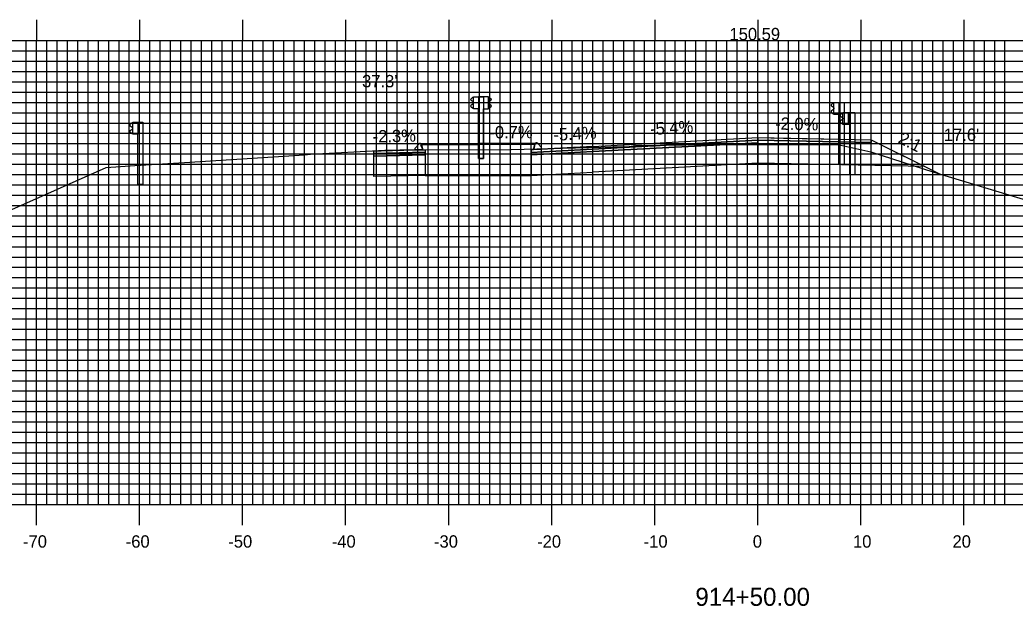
# Model space of a CAD drawing. Extents: x 860652 to 860995, y 364765 to 364985.
# Drawn here: x 860745.8 to 860842.4, y 364833.4 to 364890.3 of the extents above; entities that cross this region are included whole.
import ezdxf

# ---------------------------------------------------------------- set-up
doc = ezdxf.new("R2010")
doc.units = 0
for name, color, linetype in [('ANNOTATION', 7, 'Continuous'), ('D_Curb_Type_3M2_Lt', 7, 'Continuous'), ('D_Curb_Type_3M2_Rt', 7, 'Continuous'), ('D_Guardrail_Beam_Rt', 7, 'Continuous'), ('D_Roadway_Centerline', 7, 'Continuous'), ('D_Roadway_Centerline_Text', 7, 'Continuous'), ('D_Roadway_Edge_Shoulder', 7, 'Continuous'), ('D_Roadway_Edge_TW', 7, 'Continuous'), ('D_Roadway_FinishedGrade', 7, 'Continuous'), ('D_Roadway_Pavement', 7, 'Continuous'), ('D_Roadway_SlopeLines', 7, 'Continuous'), ('D_Roadway_SubGrade', 7, 'Continuous'), ('D_Text_Standard', 7, 'Continuous'), ('H_V ANNOTATION', 7, 'Continuous'), ('M_Guardrail', 7, 'Continuous'), ('M_Roadway_Centerline', 7, 'Continuous'), ('MAJOR', 7, 'Continuous'), ('MINOR', 7, 'Continuous'), ('S_Roadway_Centerline', 7, 'Continuous')]:
    doc.layers.add(name, color=color, linetype=linetype)

msp = doc.modelspace()

# ---------------------------------------------------------------- linework, layer by layer
at = {"layer": 'D_Curb_Type_3M2_Lt'}
for p, q in [((860795.77, 364878.255), (860795.662, 364877.761)), ((860795.662, 364877.761), (860796.412, 364877.761)), ((860795.906, 364878.384), (860795.911, 364878.384)), ((860796.412, 364877.928), (860796.058, 364878.33)), ((860796.412, 364877.761), (860796.412, 364877.928))]:
    msp.add_line(p, q, dxfattribs=at)
msp.add_arc((860795.933, 364878.22), 0.167, 41.38705, 167.66476, dxfattribs=at)
at = {"layer": 'D_Curb_Type_3M2_Rt'}
for p, q in [((860784.145, 364877.859), (860784.499, 364878.261)), ((860784.145, 364877.692), (860784.145, 364877.859)), ((860784.895, 364877.692), (860784.145, 364877.692)), ((860784.787, 364878.186), (860784.895, 364877.692))]:
    msp.add_line(p, q, dxfattribs=at)
msp.add_arc((860784.624, 364878.151), 0.167, 12.33524, 138.61295, dxfattribs=at)
at = {"layer": 'D_Guardrail_Beam_Rt'}
for p, q in [((860825.594, 364881.214), (860825.45, 364881.114)), ((860825.45, 364880.971), (860825.646, 364880.835)), ((860825.646, 364880.636), (860825.45, 364880.5)), ((860825.684, 364881.235), (860825.609, 364881.221)), ((860825.679, 364880.77), (860825.679, 364880.7)), ((860825.684, 364881.319), (860826.371, 364881.319)), ((860825.684, 364880.152), (860825.684, 364881.319)), ((860826.204, 364881.319), (860826.204, 364880.152)), ((860826.309, 364881.319), (860826.309, 364880.152)), ((860826.371, 364881.319), (860826.842, 364881.319)), ((860826.371, 364881.319), (860826.371, 364880.152)), ((860826.842, 364881.319), (860826.842, 364875.319)), ((860825.45, 364880.356), (860825.594, 364880.257)), ((860825.609, 364880.25), (860825.684, 364880.235)), ((860826.371, 364880.152), (860825.684, 364880.152)), ((860826.35, 364875.319), (860826.35, 364880.152)), ((860826.35, 364875.319), (860826.842, 364875.319))]:
    msp.add_line(p, q, dxfattribs=at)
for centre, major_axis, start_param, end_param in [((860825.5, 364881.042), (-0.0877, 0), 5.323254, 7.243116), ((860825.5, 364880.428), (-0.0877, 0), 5.323254, 7.243116), ((860825.618, 364881.18), (-0.0417, 0), 4.907132, 5.323254), ((860825.6, 364880.77), (0.0789, 0), 0, 0.959931), ((860825.6, 364880.7), (0.0789, 0), 5.323254, 6.283185), ((860825.618, 364880.29), (-0.0417, 0), 0.959931, 1.376053)]:
    msp.add_ellipse(centre, major_axis=major_axis, ratio=0.995501, start_param=start_param, end_param=end_param, dxfattribs=at)
at = {"layer": 'D_Roadway_Centerline'}
for points in [[(860796.412, 364877.761), (860796.423, 364877.762), (860799.387, 364877.922), (860801.412, 364878.031), (860801.413, 364878.031), (860817.41, 364878.895), (860817.413, 364878.895), (860819.903, 364878.845), (860825.396, 364878.736), (860825.413, 364878.735), (860828.404, 364878.675), (860828.412, 364878.675), (860828.425, 364878.669), (860833.621, 364876.071), (860833.627, 364876.068), (860834.976, 364875.393)], [(860780.145, 364877.601), (860780.858, 364877.618), (860784.145, 364877.692)]]:
    msp.add_lwpolyline(points, dxfattribs=at)
at = {"layer": 'D_Roadway_Edge_Shoulder'}
for points in [[(860817.413, 364878.895), (860825.413, 364878.735), (860825.413, 364878.735), (860828.412, 364878.675), (860828.412, 364878.425), (860817.413, 364878.645)], [(860780.145, 364877.601), (860784.145, 364877.692), (860785.145, 364877.715), (860785.145, 364877.465), (860780.145, 364877.351)], [(860801.413, 364878.031), (860796.412, 364877.761), (860795.413, 364877.707), (860795.413, 364877.457), (860801.413, 364877.781)]]:
    msp.add_lwpolyline(points, close=True, dxfattribs=at)
at = {"layer": 'D_Roadway_Edge_TW'}
msp.add_lwpolyline([(860801.413, 364878.031), (860817.413, 364878.895), (860817.413, 364878.645), (860801.413, 364877.781)], close=True, dxfattribs=at)
at = {"layer": 'D_Roadway_FinishedGrade'}
msp.add_lwpolyline([(860784.666, 364878.312), (860795.891, 364878.381)], dxfattribs=at)
at = {"layer": 'D_Roadway_Pavement'}
for points in [[(860801.413, 364877.781), (860817.413, 364878.645), (860817.413, 364878.395), (860801.413, 364877.531)], [(860801.413, 364877.781), (860795.413, 364877.457), (860795.413, 364877.207), (860801.413, 364877.531)], [(860780.145, 364877.351), (860785.145, 364877.465), (860785.145, 364877.215), (860780.145, 364877.101)]]:
    msp.add_lwpolyline(points, close=True, dxfattribs=at)
msp.add_lwpolyline([(860817.413, 364878.645), (860817.413, 364878.395)], dxfattribs=at)
msp.add_lwpolyline([(860817.413, 364878.645), (860817.413, 364878.395)], dxfattribs=at)
at = {"layer": 'D_Roadway_SlopeLines'}
msp.add_lwpolyline([(860828.412, 364878.675), (860834.976, 364875.393)], dxfattribs=at)
at = {"layer": 'D_Roadway_SubGrade'}
for points in [[(860817.413, 364878.395), (860817.413, 364878.645), (860828.412, 364878.425), (860828.412, 364878.675), (860833.621, 364876.071), (860817.413, 364876.395)], [(860785.145, 364877.715), (860785.145, 364875.215), (860795.413, 364875.207), (860795.413, 364877.207), (860795.413, 364877.457), (860795.413, 364877.707), (860795.653, 364877.72), (860795.761, 364878.213), (860784.667, 364878.145), (860784.891, 364877.709)], [(860801.413, 364877.531), (860817.413, 364878.395), (860817.413, 364876.395), (860801.413, 364875.531)], [(860780.145, 364877.101), (860785.145, 364877.215), (860785.145, 364877.465), (860785.145, 364875.215), (860780.145, 364875.101)], [(860801.413, 364877.531), (860795.413, 364877.207), (860795.413, 364877.457), (860795.413, 364875.207), (860801.413, 364875.531)]]:
    msp.add_lwpolyline(points, close=True, dxfattribs=at)
at = {"layer": 'M_Guardrail'}
for p, q in [((860789.725, 364882.763), (860789.582, 364882.663)), ((860789.582, 364882.52), (860789.777, 364882.384)), ((860789.824, 364882.785), (860789.742, 364882.77)), ((860789.824, 364882.857), (860790.314, 364882.857)), ((860789.824, 364881.691), (860789.824, 364882.857)), ((860790.301, 364882.859), (860790.301, 364876.859)), ((860790.793, 364882.859), (860790.301, 364882.859)), ((860790.314, 364882.857), (860790.805, 364882.857)), ((860790.314, 364882.857), (860790.314, 364881.691)), ((860791.282, 364882.859), (860790.793, 364882.859)), ((860790.793, 364882.859), (860790.793, 364881.692)), ((860790.805, 364882.857), (860790.805, 364876.857)), ((860791.282, 364881.692), (860791.282, 364882.859)), ((860791.282, 364882.786), (860791.364, 364882.771)), ((860791.525, 364882.521), (860791.329, 364882.385)), ((860791.381, 364882.765), (860791.525, 364882.665)), ((860789.777, 364882.164), (860789.582, 364882.028)), ((860789.582, 364881.885), (860789.725, 364881.785)), ((860789.742, 364881.778), (860789.824, 364881.764)), ((860789.811, 364882.32), (860789.811, 364882.229)), ((860790.314, 364881.691), (860789.824, 364881.691)), ((860790.314, 364876.857), (860790.314, 364881.691)), ((860790.793, 364876.859), (860790.793, 364881.692)), ((860790.793, 364881.692), (860791.282, 364881.692)), ((860791.364, 364881.779), (860791.282, 364881.765)), ((860791.296, 364882.321), (860791.296, 364882.23)), ((860791.329, 364882.165), (860791.525, 364882.029)), ((860791.525, 364881.886), (860791.381, 364881.786)), ((860824.708, 364882.213), (860824.565, 364882.113)), ((860824.565, 364881.97), (860824.76, 364881.834)), ((860824.76, 364881.614), (860824.565, 364881.478)), ((860824.807, 364882.234), (860824.725, 364882.22)), ((860824.794, 364881.77), (860824.794, 364881.678)), ((860824.807, 364882.307), (860825.297, 364882.307)), ((860824.807, 364881.141), (860824.807, 364882.307)), ((860825.297, 364882.307), (860825.788, 364882.307)), ((860825.297, 364882.307), (860825.297, 364881.141)), ((860825.788, 364882.307), (860825.788, 364876.307)), ((860824.565, 364881.335), (860824.708, 364881.235)), ((860824.725, 364881.228), (860824.807, 364881.214)), ((860825.297, 364881.141), (860824.807, 364881.141)), ((860825.297, 364876.307), (860825.297, 364881.141)), ((860756.645, 364880.285), (860756.502, 364880.185)), ((860756.502, 364880.042), (860756.697, 364879.906)), ((860756.697, 364879.686), (860756.502, 364879.55)), ((860756.744, 364880.306), (860756.662, 364880.292)), ((860756.731, 364879.841), (860756.731, 364879.75)), ((860756.744, 364880.379), (860757.234, 364880.379)), ((860756.744, 364879.213), (860756.744, 364880.379)), ((860757.234, 364880.379), (860757.725, 364880.379)), ((860757.234, 364880.379), (860757.234, 364879.213)), ((860757.725, 364880.379), (860757.725, 364874.379)), ((860756.502, 364879.407), (860756.645, 364879.307)), ((860756.662, 364879.3), (860756.744, 364879.285)), ((860757.234, 364879.213), (860756.744, 364879.213)), ((860757.234, 364874.379), (860757.234, 364879.213)), ((860790.793, 364876.859), (860790.301, 364876.859)), ((860790.314, 364876.857), (860790.805, 364876.857)), ((860825.297, 364876.307), (860825.788, 364876.307)), ((860757.234, 364874.379), (860757.725, 364874.379))]:
    msp.add_line(p, q, dxfattribs=at)
for centre, major_axis, start_param, end_param in [((860789.632, 364882.592), (-0.0877, 0), 5.323254, 7.243116), ((860789.749, 364882.729), (-0.0417, 0), 4.886922, 5.323254), ((860791.357, 364882.731), (0.0417, 0), 0.959931, 1.396263), ((860791.474, 364882.593), (0.0877, 0), 5.323254, 7.243116), ((860789.632, 364881.957), (-0.0877, 0), 5.323254, 7.243116), ((860789.749, 364881.819), (-0.0417, 0), 0.959931, 1.396263), ((860789.732, 364882.32), (0.0789, 0), 0, 0.959931), ((860789.732, 364882.229), (0.0789, 0), 5.323254, 6.283185), ((860791.374, 364882.321), (-0.0789, 0), 5.323254, 6.283185), ((860791.374, 364882.23), (-0.0789, 0), 6.283185, 7.243116), ((860791.357, 364881.82), (0.0417, 0), 4.886922, 5.323254), ((860791.474, 364881.958), (0.0877, 0), 5.323254, 7.243116), ((860824.615, 364882.042), (-0.0877, 0), 5.323254, 7.243116), ((860824.615, 364881.406), (-0.0877, 0), 5.323254, 7.243116), ((860824.732, 364882.179), (-0.0417, 0), 4.886922, 5.323254), ((860824.715, 364881.77), (0.0789, 0), 0, 0.959931), ((860824.715, 364881.678), (0.0789, 0), 5.323254, 6.283185), ((860824.732, 364881.269), (-0.0417, 0), 0.959931, 1.396263), ((860756.552, 364880.113), (-0.0877, 0), 5.323254, 7.243116), ((860756.552, 364879.478), (-0.0877, 0), 5.323254, 7.243116), ((860756.669, 364880.251), (-0.0417, 0), 4.886922, 5.323254), ((860756.652, 364879.841), (0.0789, 0), 0, 0.959931), ((860756.652, 364879.75), (0.0789, 0), 5.323254, 6.283185), ((860756.669, 364879.341), (-0.0417, 0), 0.959931, 1.396263)]:
    msp.add_ellipse(centre, major_axis=major_axis, ratio=0.995501, start_param=start_param, end_param=end_param, dxfattribs=at)
at = {"layer": 'MAJOR'}
for p, q in [((860747.412, 364890.306), (860747.412, 364888.302)), ((860757.412, 364890.306), (860757.412, 364888.302)), ((860767.412, 364890.306), (860767.412, 364888.302)), ((860777.412, 364890.306), (860777.412, 364888.302)), ((860787.412, 364890.306), (860787.412, 364888.302)), ((860797.412, 364890.306), (860797.412, 364888.302)), ((860807.412, 364890.306), (860807.412, 364888.302)), ((860817.412, 364890.306), (860817.412, 364888.302)), ((860827.412, 364890.306), (860827.412, 364888.302)), ((860837.412, 364890.306), (860837.412, 364888.302)), ((860677.412, 364888.302), (860957.412, 364888.302)), ((860677.412, 364888.302), (860957.412, 364888.302)), ((860747.412, 364843.302), (860747.412, 364888.302)), ((860757.412, 364843.302), (860757.412, 364888.302)), ((860767.412, 364843.302), (860767.412, 364888.302)), ((860777.412, 364843.302), (860777.412, 364888.302)), ((860787.412, 364843.302), (860787.412, 364888.302)), ((860797.412, 364843.302), (860797.412, 364888.302)), ((860807.412, 364843.302), (860807.412, 364888.302)), ((860817.412, 364843.302), (860817.412, 364888.302)), ((860827.412, 364843.302), (860827.412, 364888.302)), ((860837.412, 364843.302), (860837.412, 364888.302)), ((860677.412, 364883.302), (860957.412, 364883.302)), ((860677.412, 364878.302), (860957.412, 364878.302)), ((860677.412, 364873.302), (860957.412, 364873.302)), ((860677.412, 364868.302), (860957.412, 364868.302)), ((860677.412, 364863.302), (860957.412, 364863.302)), ((860677.412, 364858.302), (860957.412, 364858.302)), ((860677.412, 364853.302), (860957.412, 364853.302)), ((860677.412, 364848.302), (860957.412, 364848.302)), ((860677.412, 364843.302), (860957.412, 364843.302)), ((860677.412, 364843.302), (860957.412, 364843.302)), ((860747.412, 364841.298), (860747.412, 364843.302)), ((860757.412, 364841.298), (860757.412, 364843.302)), ((860767.412, 364841.298), (860767.412, 364843.302)), ((860777.412, 364841.298), (860777.412, 364843.302)), ((860787.412, 364841.298), (860787.412, 364843.302)), ((860797.412, 364841.298), (860797.412, 364843.302)), ((860807.412, 364841.298), (860807.412, 364843.302)), ((860817.412, 364841.298), (860817.412, 364843.302)), ((860827.412, 364841.298), (860827.412, 364843.302)), ((860837.412, 364841.298), (860837.412, 364843.302))]:
    msp.add_line(p, q, dxfattribs=at)
at = {"layer": 'MINOR'}
for p, q in [((860746.412, 364843.302), (860746.412, 364888.302)), ((860748.412, 364843.302), (860748.412, 364888.302)), ((860749.412, 364843.302), (860749.412, 364888.302)), ((860750.412, 364843.302), (860750.412, 364888.302)), ((860751.412, 364843.302), (860751.412, 364888.302)), ((860752.412, 364843.302), (860752.412, 364888.302)), ((860753.412, 364843.302), (860753.412, 364888.302)), ((860754.412, 364843.302), (860754.412, 364888.302)), ((860755.412, 364843.302), (860755.412, 364888.302)), ((860756.412, 364843.302), (860756.412, 364888.302)), ((860758.412, 364843.302), (860758.412, 364888.302)), ((860759.412, 364843.302), (860759.412, 364888.302)), ((860760.412, 364843.302), (860760.412, 364888.302)), ((860761.412, 364843.302), (860761.412, 364888.302)), ((860762.412, 364843.302), (860762.412, 364888.302)), ((860763.412, 364843.302), (860763.412, 364888.302)), ((860764.412, 364843.302), (860764.412, 364888.302)), ((860765.412, 364843.302), (860765.412, 364888.302)), ((860766.412, 364843.302), (860766.412, 364888.302)), ((860768.412, 364843.302), (860768.412, 364888.302)), ((860769.412, 364843.302), (860769.412, 364888.302)), ((860770.412, 364843.302), (860770.412, 364888.302)), ((860771.412, 364843.302), (860771.412, 364888.302)), ((860772.412, 364843.302), (860772.412, 364888.302)), ((860773.412, 364843.302), (860773.412, 364888.302)), ((860774.412, 364843.302), (860774.412, 364888.302)), ((860775.412, 364843.302), (860775.412, 364888.302)), ((860776.412, 364843.302), (860776.412, 364888.302)), ((860778.412, 364843.302), (860778.412, 364888.302)), ((860779.412, 364843.302), (860779.412, 364888.302)), ((860780.412, 364843.302), (860780.412, 364888.302)), ((860781.412, 364843.302), (860781.412, 364888.302)), ((860782.412, 364843.302), (860782.412, 364888.302)), ((860783.412, 364843.302), (860783.412, 364888.302)), ((860784.412, 364843.302), (860784.412, 364888.302)), ((860785.412, 364843.302), (860785.412, 364888.302)), ((860786.412, 364843.302), (860786.412, 364888.302)), ((860788.412, 364843.302), (860788.412, 364888.302)), ((860789.412, 364843.302), (860789.412, 364888.302)), ((860790.412, 364843.302), (860790.412, 364888.302)), ((860791.412, 364843.302), (860791.412, 364888.302)), ((860792.412, 364843.302), (860792.412, 364888.302)), ((860793.412, 364843.302), (860793.412, 364888.302)), ((860794.412, 364843.302), (860794.412, 364888.302)), ((860795.412, 364843.302), (860795.412, 364888.302)), ((860796.412, 364843.302), (860796.412, 364888.302)), ((860798.412, 364843.302), (860798.412, 364888.302)), ((860799.412, 364843.302), (860799.412, 364888.302)), ((860800.412, 364843.302), (860800.412, 364888.302)), ((860801.412, 364843.302), (860801.412, 364888.302)), ((860802.412, 364843.302), (860802.412, 364888.302)), ((860803.412, 364843.302), (860803.412, 364888.302)), ((860804.412, 364843.302), (860804.412, 364888.302)), ((860805.412, 364843.302), (860805.412, 364888.302)), ((860806.412, 364843.302), (860806.412, 364888.302)), ((860808.412, 364843.302), (860808.412, 364888.302)), ((860809.412, 364843.302), (860809.412, 364888.302)), ((860810.412, 364843.302), (860810.412, 364888.302)), ((860811.412, 364843.302), (860811.412, 364888.302)), ((860812.412, 364843.302), (860812.412, 364888.302)), ((860813.412, 364843.302), (860813.412, 364888.302)), ((860814.412, 364843.302), (860814.412, 364888.302)), ((860815.412, 364843.302), (860815.412, 364888.302)), ((860816.412, 364843.302), (860816.412, 364888.302)), ((860818.412, 364843.302), (860818.412, 364888.302)), ((860819.412, 364843.302), (860819.412, 364888.302)), ((860820.412, 364843.302), (860820.412, 364888.302)), ((860821.412, 364843.302), (860821.412, 364888.302)), ((860822.412, 364843.302), (860822.412, 364888.302)), ((860823.412, 364843.302), (860823.412, 364888.302)), ((860824.412, 364843.302), (860824.412, 364888.302)), ((860825.412, 364843.302), (860825.412, 364888.302)), ((860826.412, 364843.302), (860826.412, 364888.302)), ((860828.412, 364843.302), (860828.412, 364888.302)), ((860829.412, 364843.302), (860829.412, 364888.302)), ((860830.412, 364843.302), (860830.412, 364888.302)), ((860831.412, 364843.302), (860831.412, 364888.302)), ((860832.412, 364843.302), (860832.412, 364888.302)), ((860833.412, 364843.302), (860833.412, 364888.302)), ((860834.412, 364843.302), (860834.412, 364888.302)), ((860835.412, 364843.302), (860835.412, 364888.302)), ((860836.412, 364843.302), (860836.412, 364888.302)), ((860838.412, 364843.302), (860838.412, 364888.302)), ((860839.412, 364843.302), (860839.412, 364888.302)), ((860840.412, 364843.302), (860840.412, 364888.302)), ((860841.412, 364843.302), (860841.412, 364888.302)), ((860677.412, 364887.302), (860957.412, 364887.302)), ((860677.412, 364886.302), (860957.412, 364886.302)), ((860677.412, 364885.302), (860957.412, 364885.302)), ((860677.412, 364884.302), (860957.412, 364884.302)), ((860677.412, 364882.302), (860957.412, 364882.302)), ((860677.412, 364881.302), (860957.412, 364881.302)), ((860677.412, 364880.302), (860957.412, 364880.302)), ((860677.412, 364879.302), (860957.412, 364879.302)), ((860677.412, 364877.302), (860957.412, 364877.302)), ((860677.412, 364876.302), (860957.412, 364876.302)), ((860677.412, 364875.302), (860957.412, 364875.302)), ((860677.412, 364874.302), (860957.412, 364874.302)), ((860677.412, 364872.302), (860957.412, 364872.302)), ((860677.412, 364871.302), (860957.412, 364871.302)), ((860677.412, 364870.302), (860957.412, 364870.302)), ((860677.412, 364869.302), (860957.412, 364869.302)), ((860677.412, 364867.302), (860957.412, 364867.302)), ((860677.412, 364866.302), (860957.412, 364866.302)), ((860677.412, 364865.302), (860957.412, 364865.302)), ((860677.412, 364864.302), (860957.412, 364864.302)), ((860677.412, 364862.302), (860957.412, 364862.302)), ((860677.412, 364861.302), (860957.412, 364861.302)), ((860677.412, 364860.302), (860957.412, 364860.302)), ((860677.412, 364859.302), (860957.412, 364859.302)), ((860677.412, 364857.302), (860957.412, 364857.302)), ((860677.412, 364856.302), (860957.412, 364856.302)), ((860677.412, 364855.302), (860957.412, 364855.302)), ((860677.412, 364854.302), (860957.412, 364854.302)), ((860677.412, 364852.302), (860957.412, 364852.302)), ((860677.412, 364851.302), (860957.412, 364851.302)), ((860677.412, 364850.302), (860957.412, 364850.302)), ((860677.412, 364849.302), (860957.412, 364849.302)), ((860677.412, 364847.302), (860957.412, 364847.302)), ((860677.412, 364846.302), (860957.412, 364846.302)), ((860677.412, 364845.302), (860957.412, 364845.302)), ((860677.412, 364844.302), (860957.412, 364844.302))]:
    msp.add_line(p, q, dxfattribs=at)
at = {"layer": 'S_Roadway_Centerline'}
msp.add_lwpolyline([(860744.729, 364871.795), (860754.16, 364876.001), (860756.933, 364876.197), (860761.774, 364876.487), (860773.426, 364877.231), (860773.994, 364877.28), (860781.223, 364877.658), (860782.665, 364877.686), (860793.473, 364877.736), (860803.49, 364877.98), (860804.92, 364878.034), (860805.557, 364878.135), (860810.428, 364878.191), (860822.906, 364878.212), (860825.178, 364878.233), (860828.393, 364877.497), (860834.52, 364875.531), (860843.915, 364872.696)], dxfattribs=at)

# ---------------------------------------------------------------- texts
at = {"layer": 'ANNOTATION'}
for s, rotation, p in [('-5.4%', 3.091, (860806.995, 364879.136)), ('-2.0%', 358.85432, (860819.09, 364879.662)), ('-2.3%', 1.30194, (860780.049, 364878.4)), ('-0.7%', 0.41422, (860791.371, 364878.806)), ('-5.4%', 3.09067, (860797.604, 364878.569)), ('2:1', 333.43902, (860830.957, 364878.439))]:
    msp.add_text(s, height=1.2, rotation=rotation, dxfattribs=at).set_placement(p)
at = {"layer": 'D_Roadway_Centerline_Text'}
msp.add_text('150.59', height=1.2, dxfattribs=at).set_placement((860814.672, 364888.331))
at = {"layer": 'D_Text_Standard'}
for s, p in [("37.3'", (860779.009, 364883.767)), ("17.6'", (860835.475, 364878.565))]:
    msp.add_text(s, height=1.2, dxfattribs=at).set_placement(p)
at = {"layer": 'H_V ANNOTATION'}
for s, height, p in [('-70', 1.2, (860746.096, 364839.102)), ('-60', 1.2, (860756.064, 364839.102)), ('-50', 1.2, (860766.021, 364839.102)), ('-40', 1.2, (860776.064, 364839.102)), ('-30', 1.2, (860785.989, 364839.102)), ('-20', 1.2, (860795.999, 364839.102)), ('-10', 1.2, (860806.342, 364839.102)), ('0', 1.2, (860816.931, 364839.102)), ('10', 1.2, (860826.663, 364839.102)), ('20', 1.2, (860836.32, 364839.102)), ('914+50.00', 1.75, (860811.357, 364833.458))]:
    msp.add_text(s, height=height, dxfattribs=at).set_placement(p)
at = {"layer": 'M_Roadway_Centerline'}
for s, p in [('C', (860805.552, 364878.135)), ('L', (860805.557, 364878.127)), ('C', (860773.989, 364877.28)), ('L', (860773.994, 364877.273))]:
    msp.add_text(s, height=0.0146, dxfattribs=at).set_placement(p)

doc.saveas('drawing.dxf')
